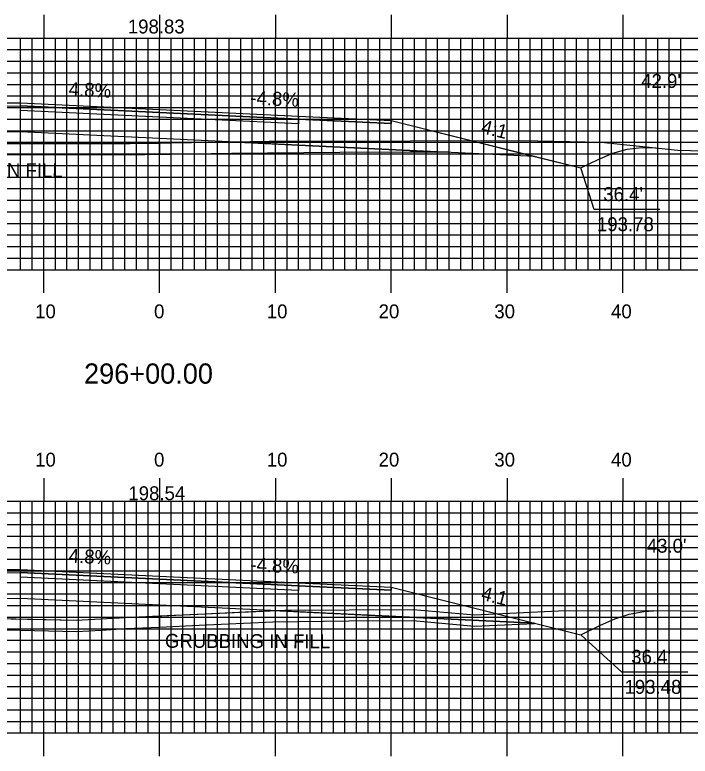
# Model space of a CAD drawing. Extents: x 1814522 to 1814865, y 442591 to 442811.
# Drawn here: x 1814675 to 1814733.3, y 442686.7 to 442750.7 of the extents above; entities that cross this region are included whole.
import ezdxf

# ---------------------------------------------------------------- set-up
doc = ezdxf.new("R2010")
doc.units = 0
for name, color, linetype in [('ANNOTATION', 7, 'Continuous'), ('D_Roadway_Centerline', 7, 'Continuous'), ('D_Roadway_Centerline_Text', 7, 'Continuous'), ('D_Roadway_Edge_Shoulder', 7, 'Continuous'), ('D_Roadway_Edge_TW', 7, 'Continuous'), ('D_Roadway_Pavement', 7, 'Continuous'), ('D_Roadway_SlopeLines', 7, 'Continuous'), ('D_Roadway_SubGrade', 7, 'Continuous'), ('D_Text_Standard', 7, 'Continuous'), ('GRUBBING IN FILL', 7, 'Continuous'), ('H_V ANNOTATION', 7, 'Continuous'), ('MAJOR', 7, 'Continuous'), ('MINOR', 7, 'Continuous'), ('S_Roadway_Centerline', 7, 'Continuous')]:
    doc.layers.add(name, color=color, linetype=linetype)

msp = doc.modelspace()

# ---------------------------------------------------------------- linework, layer by layer
at = {"layer": 'ANNOTATION'}
for points in [[(1814730.701, 442733.864), (1814725.009, 442733.864), (1814723.884, 442737.445)], [(1814733.115, 442693.92), (1814727.424, 442693.92), (1814723.884, 442697.147)]]:
    msp.add_lwpolyline(points, dxfattribs=at)
at = {"layer": 'D_Roadway_Centerline'}
for points in [[(1814653.448, 442739.4), (1814656.638, 442740.197), (1814667.508, 442742.915), (1814675.508, 442743.075), (1814687.508, 442742.499), (1814699.508, 442741.923), (1814707.508, 442741.539), (1814719.884, 442738.445), (1814723.884, 442737.445), (1814725.374, 442738.19), (1814726.624, 442738.721), (1814727.874, 442739.063), (1814729.124, 442739.217), (1814730.374, 442739.183)], [(1814652.747, 442698.927), (1814656.638, 442699.899), (1814667.508, 442702.617), (1814675.508, 442702.777), (1814687.508, 442702.201), (1814699.508, 442701.625), (1814707.508, 442701.241), (1814719.884, 442698.147), (1814723.884, 442697.147), (1814725.557, 442697.984), (1814726.807, 442698.531), (1814728.057, 442698.923), (1814729.307, 442699.16), (1814730.557, 442699.241)]]:
    msp.add_lwpolyline(points, dxfattribs=at)
at = {"layer": 'D_Roadway_Edge_Shoulder'}
for points in [[(1814675.508, 442743.075), (1814667.508, 442742.915), (1814667.508, 442742.665), (1814675.508, 442742.825)], [(1814699.508, 442741.923), (1814707.508, 442741.539), (1814707.508, 442741.289), (1814699.508, 442741.673)], [(1814675.508, 442702.777), (1814667.508, 442702.617), (1814667.508, 442702.367), (1814675.508, 442702.527)], [(1814699.508, 442701.625), (1814707.508, 442701.241), (1814707.508, 442700.991), (1814699.508, 442701.375)]]:
    msp.add_lwpolyline(points, close=True, dxfattribs=at)
at = {"layer": 'D_Roadway_Edge_TW'}
for points in [[(1814675.508, 442742.825), (1814675.508, 442743.075), (1814687.508, 442742.499), (1814699.508, 442741.923), (1814699.508, 442741.673), (1814687.508, 442742.249)], [(1814675.508, 442702.527), (1814675.508, 442702.777), (1814687.508, 442702.201), (1814699.508, 442701.625), (1814699.508, 442701.375), (1814687.508, 442701.951)]]:
    msp.add_lwpolyline(points, close=True, dxfattribs=at)
at = {"layer": 'D_Roadway_Pavement'}
for points in [[(1814675.508, 442742.408), (1814675.508, 442742.825), (1814687.508, 442742.249), (1814699.508, 442741.673), (1814699.508, 442741.256), (1814687.508, 442741.832)], [(1814675.508, 442702.11), (1814675.508, 442702.527), (1814687.508, 442701.951), (1814699.508, 442701.375), (1814699.508, 442700.958), (1814687.508, 442701.534)]]:
    msp.add_lwpolyline(points, close=True, dxfattribs=at)
at = {"layer": 'D_Roadway_SlopeLines'}
for points in [[(1814707.508, 442741.539), (1814723.884, 442737.445)], [(1814723.884, 442737.445), (1814725.374, 442738.19), (1814726.624, 442738.721), (1814727.874, 442739.063), (1814729.124, 442739.217), (1814730.374, 442739.183)], [(1814707.508, 442701.241), (1814723.884, 442697.147)], [(1814723.884, 442697.147), (1814725.557, 442697.984), (1814726.807, 442698.531), (1814728.057, 442698.923), (1814729.307, 442699.16), (1814730.557, 442699.241)]]:
    msp.add_lwpolyline(points, dxfattribs=at)
at = {"layer": 'D_Roadway_SubGrade'}
for points in [[(1814675.508, 442740.575), (1814656.638, 442740.197), (1814667.508, 442742.915), (1814667.508, 442742.665), (1814675.508, 442742.825), (1814687.508, 442742.249), (1814699.508, 442741.673), (1814707.508, 442741.289), (1814707.508, 442741.539), (1814719.884, 442738.445), (1814699.508, 442739.423), (1814687.508, 442739.999)], [(1814675.508, 442700.277), (1814656.638, 442699.899), (1814667.508, 442702.617), (1814667.508, 442702.367), (1814675.508, 442702.527), (1814687.508, 442701.951), (1814699.508, 442701.375), (1814707.508, 442700.991), (1814707.508, 442701.241), (1814719.884, 442698.147), (1814699.508, 442699.125), (1814687.508, 442699.701)]]:
    msp.add_lwpolyline(points, close=True, dxfattribs=at)
at = {"layer": 'GRUBBING IN FILL'}
for points in [[(1814656.638, 442739.528), (1814658.134, 442739.6), (1814671.642, 442739.571), (1814684.967, 442739.552), (1814687.508, 442739.596), (1814687.508, 442738.596), (1814684.975, 442738.552), (1814671.633, 442738.571), (1814658.291, 442738.591), (1814656.638, 442738.527)], [(1814656.638, 442739.528), (1814658.134, 442739.6), (1814671.642, 442739.571), (1814684.967, 442739.552), (1814687.508, 442739.596), (1814687.508, 442738.596), (1814684.975, 442738.552), (1814671.633, 442738.571), (1814658.291, 442738.591), (1814656.638, 442738.527)], [(1814687.508, 442739.596), (1814688.487, 442739.613), (1814693.703, 442739.701), (1814699.508, 442739.423), (1814709.696, 442738.934), (1814712.474, 442738.8), (1814709.167, 442738.797), (1814703.066, 442738.775), (1814693.703, 442738.701), (1814688.499, 442738.613), (1814687.508, 442738.596)], [(1814687.508, 442739.596), (1814688.487, 442739.613), (1814693.703, 442739.701), (1814699.508, 442739.423), (1814709.696, 442738.934), (1814712.474, 442738.8), (1814709.167, 442738.797), (1814703.066, 442738.775), (1814693.703, 442738.701), (1814688.499, 442738.613), (1814687.508, 442738.596)], [(1814687.508, 442698.782), (1814691.419, 442698.962), (1814697.283, 442699.232), (1814709.696, 442698.636), (1814719.884, 442698.147), (1814719.884, 442698.099), (1814714.679, 442697.853), (1814709.368, 442698.333), (1814703.85, 442698.306), (1814697.283, 442698.231), (1814690.933, 442697.938), (1814687.508, 442697.781)], [(1814687.508, 442698.782), (1814691.419, 442698.962), (1814697.283, 442699.232), (1814709.696, 442698.636), (1814719.884, 442698.147), (1814719.884, 442698.099), (1814714.679, 442697.853), (1814709.368, 442698.333), (1814703.85, 442698.306), (1814697.283, 442698.231), (1814690.933, 442697.938), (1814687.508, 442697.781)], [(1814656.638, 442698.871), (1814663.185, 442698.778), (1814671.839, 442698.589), (1814680.303, 442698.403), (1814684.531, 442698.645), (1814687.508, 442698.782), (1814687.508, 442697.781), (1814684.582, 442697.646), (1814682.451, 442697.525), (1814680.32, 442697.403), (1814671.838, 442697.589), (1814663.17, 442697.778), (1814656.638, 442697.871)], [(1814656.638, 442698.871), (1814663.185, 442698.778), (1814671.839, 442698.589), (1814680.303, 442698.403), (1814684.531, 442698.645), (1814687.508, 442698.782), (1814687.508, 442697.781), (1814684.582, 442697.646), (1814682.451, 442697.525), (1814680.32, 442697.403), (1814671.838, 442697.589), (1814663.17, 442697.778), (1814656.638, 442697.871)]]:
    msp.add_lwpolyline(points, close=True, dxfattribs=at)
at = {"layer": 'MAJOR'}
for p, q in [((1814677.508, 442750.669), (1814677.508, 442748.665)), ((1814687.508, 442750.669), (1814687.508, 442748.665)), ((1814697.508, 442750.669), (1814697.508, 442748.665)), ((1814707.508, 442750.669), (1814707.508, 442748.665)), ((1814717.508, 442750.669), (1814717.508, 442748.665)), ((1814727.508, 442750.669), (1814727.508, 442748.665)), ((1814547.508, 442748.665), (1814827.508, 442748.665)), ((1814547.508, 442748.665), (1814827.508, 442748.665)), ((1814677.508, 442728.665), (1814677.508, 442748.665)), ((1814687.508, 442728.665), (1814687.508, 442748.665)), ((1814697.508, 442728.665), (1814697.508, 442748.665)), ((1814707.508, 442728.665), (1814707.508, 442748.665)), ((1814717.508, 442728.665), (1814717.508, 442748.665)), ((1814727.508, 442728.665), (1814727.508, 442748.665)), ((1814547.508, 442743.665), (1814827.508, 442743.665)), ((1814547.508, 442738.665), (1814827.508, 442738.665)), ((1814547.508, 442733.665), (1814827.508, 442733.665)), ((1814547.508, 442728.665), (1814827.508, 442728.665)), ((1814547.508, 442728.665), (1814827.508, 442728.665)), ((1814677.508, 442726.661), (1814677.508, 442728.665)), ((1814687.508, 442726.661), (1814687.508, 442728.665)), ((1814697.508, 442726.661), (1814697.508, 442728.665)), ((1814707.508, 442726.661), (1814707.508, 442728.665)), ((1814717.508, 442726.661), (1814717.508, 442728.665)), ((1814727.508, 442726.661), (1814727.508, 442728.665)), ((1814677.508, 442710.669), (1814677.508, 442708.665)), ((1814687.508, 442710.669), (1814687.508, 442708.665)), ((1814697.508, 442710.669), (1814697.508, 442708.665)), ((1814707.508, 442710.669), (1814707.508, 442708.665)), ((1814717.508, 442710.669), (1814717.508, 442708.665)), ((1814727.508, 442710.669), (1814727.508, 442708.665)), ((1814547.508, 442708.665), (1814827.508, 442708.665)), ((1814547.508, 442708.665), (1814827.508, 442708.665)), ((1814677.508, 442688.665), (1814677.508, 442708.665)), ((1814687.508, 442688.665), (1814687.508, 442708.665)), ((1814697.508, 442688.665), (1814697.508, 442708.665)), ((1814707.508, 442688.665), (1814707.508, 442708.665)), ((1814717.508, 442688.665), (1814717.508, 442708.665)), ((1814727.508, 442688.665), (1814727.508, 442708.665)), ((1814547.508, 442703.665), (1814827.508, 442703.665)), ((1814547.508, 442698.665), (1814827.508, 442698.665)), ((1814547.508, 442693.665), (1814827.508, 442693.665)), ((1814547.508, 442688.665), (1814827.508, 442688.665)), ((1814547.508, 442688.665), (1814827.508, 442688.665)), ((1814677.508, 442686.661), (1814677.508, 442688.665)), ((1814687.508, 442686.661), (1814687.508, 442688.665)), ((1814697.508, 442686.661), (1814697.508, 442688.665)), ((1814707.508, 442686.661), (1814707.508, 442688.665)), ((1814717.508, 442686.661), (1814717.508, 442688.665)), ((1814727.508, 442686.661), (1814727.508, 442688.665))]:
    msp.add_line(p, q, dxfattribs=at)
at = {"layer": 'MINOR'}
for p, q in [((1814675.508, 442728.665), (1814675.508, 442748.665)), ((1814676.508, 442728.665), (1814676.508, 442748.665)), ((1814678.508, 442728.665), (1814678.508, 442748.665)), ((1814679.508, 442728.665), (1814679.508, 442748.665)), ((1814680.508, 442728.665), (1814680.508, 442748.665)), ((1814681.508, 442728.665), (1814681.508, 442748.665)), ((1814682.508, 442728.665), (1814682.508, 442748.665)), ((1814683.508, 442728.665), (1814683.508, 442748.665)), ((1814684.508, 442728.665), (1814684.508, 442748.665)), ((1814685.508, 442728.665), (1814685.508, 442748.665)), ((1814686.508, 442728.665), (1814686.508, 442748.665)), ((1814688.508, 442728.665), (1814688.508, 442748.665)), ((1814689.508, 442728.665), (1814689.508, 442748.665)), ((1814690.508, 442728.665), (1814690.508, 442748.665)), ((1814691.508, 442728.665), (1814691.508, 442748.665)), ((1814692.508, 442728.665), (1814692.508, 442748.665)), ((1814693.508, 442728.665), (1814693.508, 442748.665)), ((1814694.508, 442728.665), (1814694.508, 442748.665)), ((1814695.508, 442728.665), (1814695.508, 442748.665)), ((1814696.508, 442728.665), (1814696.508, 442748.665)), ((1814698.508, 442728.665), (1814698.508, 442748.665)), ((1814699.508, 442728.665), (1814699.508, 442748.665)), ((1814700.508, 442728.665), (1814700.508, 442748.665)), ((1814701.508, 442728.665), (1814701.508, 442748.665)), ((1814702.508, 442728.665), (1814702.508, 442748.665)), ((1814703.508, 442728.665), (1814703.508, 442748.665)), ((1814704.508, 442728.665), (1814704.508, 442748.665)), ((1814705.508, 442728.665), (1814705.508, 442748.665)), ((1814706.508, 442728.665), (1814706.508, 442748.665)), ((1814708.508, 442728.665), (1814708.508, 442748.665)), ((1814709.508, 442728.665), (1814709.508, 442748.665)), ((1814710.508, 442728.665), (1814710.508, 442748.665)), ((1814711.508, 442728.665), (1814711.508, 442748.665)), ((1814712.508, 442728.665), (1814712.508, 442748.665)), ((1814713.508, 442728.665), (1814713.508, 442748.665)), ((1814714.508, 442728.665), (1814714.508, 442748.665)), ((1814715.508, 442728.665), (1814715.508, 442748.665)), ((1814716.508, 442728.665), (1814716.508, 442748.665)), ((1814718.508, 442728.665), (1814718.508, 442748.665)), ((1814719.508, 442728.665), (1814719.508, 442748.665)), ((1814720.508, 442728.665), (1814720.508, 442748.665)), ((1814721.508, 442728.665), (1814721.508, 442748.665)), ((1814722.508, 442728.665), (1814722.508, 442748.665)), ((1814723.508, 442728.665), (1814723.508, 442748.665)), ((1814724.508, 442728.665), (1814724.508, 442748.665)), ((1814725.508, 442728.665), (1814725.508, 442748.665)), ((1814726.508, 442728.665), (1814726.508, 442748.665)), ((1814728.508, 442728.665), (1814728.508, 442748.665)), ((1814729.508, 442728.665), (1814729.508, 442748.665)), ((1814730.508, 442728.665), (1814730.508, 442748.665)), ((1814731.508, 442728.665), (1814731.508, 442748.665)), ((1814732.508, 442728.665), (1814732.508, 442748.665)), ((1814547.508, 442747.665), (1814827.508, 442747.665)), ((1814547.508, 442746.665), (1814827.508, 442746.665)), ((1814547.508, 442745.665), (1814827.508, 442745.665)), ((1814547.508, 442744.665), (1814827.508, 442744.665)), ((1814547.508, 442742.665), (1814827.508, 442742.665)), ((1814547.508, 442741.665), (1814827.508, 442741.665)), ((1814547.508, 442740.665), (1814827.508, 442740.665)), ((1814547.508, 442739.665), (1814827.508, 442739.665)), ((1814547.508, 442737.665), (1814827.508, 442737.665)), ((1814547.508, 442736.665), (1814827.508, 442736.665)), ((1814547.508, 442735.665), (1814827.508, 442735.665)), ((1814547.508, 442734.665), (1814827.508, 442734.665)), ((1814547.508, 442732.665), (1814827.508, 442732.665)), ((1814547.508, 442731.665), (1814827.508, 442731.665)), ((1814547.508, 442730.665), (1814827.508, 442730.665)), ((1814547.508, 442729.665), (1814827.508, 442729.665)), ((1814675.508, 442688.665), (1814675.508, 442708.665)), ((1814676.508, 442688.665), (1814676.508, 442708.665)), ((1814678.508, 442688.665), (1814678.508, 442708.665)), ((1814679.508, 442688.665), (1814679.508, 442708.665)), ((1814680.508, 442688.665), (1814680.508, 442708.665)), ((1814681.508, 442688.665), (1814681.508, 442708.665)), ((1814682.508, 442688.665), (1814682.508, 442708.665)), ((1814683.508, 442688.665), (1814683.508, 442708.665)), ((1814684.508, 442688.665), (1814684.508, 442708.665)), ((1814685.508, 442688.665), (1814685.508, 442708.665)), ((1814686.508, 442688.665), (1814686.508, 442708.665)), ((1814688.508, 442688.665), (1814688.508, 442708.665)), ((1814689.508, 442688.665), (1814689.508, 442708.665)), ((1814690.508, 442688.665), (1814690.508, 442708.665)), ((1814691.508, 442688.665), (1814691.508, 442708.665)), ((1814692.508, 442688.665), (1814692.508, 442708.665)), ((1814693.508, 442688.665), (1814693.508, 442708.665)), ((1814694.508, 442688.665), (1814694.508, 442708.665)), ((1814695.508, 442688.665), (1814695.508, 442708.665)), ((1814696.508, 442688.665), (1814696.508, 442708.665)), ((1814698.508, 442688.665), (1814698.508, 442708.665)), ((1814699.508, 442688.665), (1814699.508, 442708.665)), ((1814700.508, 442688.665), (1814700.508, 442708.665)), ((1814701.508, 442688.665), (1814701.508, 442708.665)), ((1814702.508, 442688.665), (1814702.508, 442708.665)), ((1814703.508, 442688.665), (1814703.508, 442708.665)), ((1814704.508, 442688.665), (1814704.508, 442708.665)), ((1814705.508, 442688.665), (1814705.508, 442708.665)), ((1814706.508, 442688.665), (1814706.508, 442708.665)), ((1814708.508, 442688.665), (1814708.508, 442708.665)), ((1814709.508, 442688.665), (1814709.508, 442708.665)), ((1814710.508, 442688.665), (1814710.508, 442708.665)), ((1814711.508, 442688.665), (1814711.508, 442708.665)), ((1814712.508, 442688.665), (1814712.508, 442708.665)), ((1814713.508, 442688.665), (1814713.508, 442708.665)), ((1814714.508, 442688.665), (1814714.508, 442708.665)), ((1814715.508, 442688.665), (1814715.508, 442708.665)), ((1814716.508, 442688.665), (1814716.508, 442708.665)), ((1814718.508, 442688.665), (1814718.508, 442708.665)), ((1814719.508, 442688.665), (1814719.508, 442708.665)), ((1814720.508, 442688.665), (1814720.508, 442708.665)), ((1814721.508, 442688.665), (1814721.508, 442708.665)), ((1814722.508, 442688.665), (1814722.508, 442708.665)), ((1814723.508, 442688.665), (1814723.508, 442708.665)), ((1814724.508, 442688.665), (1814724.508, 442708.665)), ((1814725.508, 442688.665), (1814725.508, 442708.665)), ((1814726.508, 442688.665), (1814726.508, 442708.665)), ((1814728.508, 442688.665), (1814728.508, 442708.665)), ((1814729.508, 442688.665), (1814729.508, 442708.665)), ((1814730.508, 442688.665), (1814730.508, 442708.665)), ((1814731.508, 442688.665), (1814731.508, 442708.665)), ((1814732.508, 442688.665), (1814732.508, 442708.665)), ((1814547.508, 442707.665), (1814827.508, 442707.665)), ((1814547.508, 442706.665), (1814827.508, 442706.665)), ((1814547.508, 442705.665), (1814827.508, 442705.665)), ((1814547.508, 442704.665), (1814827.508, 442704.665)), ((1814547.508, 442702.665), (1814827.508, 442702.665)), ((1814547.508, 442701.665), (1814827.508, 442701.665)), ((1814547.508, 442700.665), (1814827.508, 442700.665)), ((1814547.508, 442699.665), (1814827.508, 442699.665)), ((1814547.508, 442697.665), (1814827.508, 442697.665)), ((1814547.508, 442696.665), (1814827.508, 442696.665)), ((1814547.508, 442695.665), (1814827.508, 442695.665)), ((1814547.508, 442694.665), (1814827.508, 442694.665)), ((1814547.508, 442692.665), (1814827.508, 442692.665)), ((1814547.508, 442691.665), (1814827.508, 442691.665)), ((1814547.508, 442690.665), (1814827.508, 442690.665)), ((1814547.508, 442689.665), (1814827.508, 442689.665))]:
    msp.add_line(p, q, dxfattribs=at)
at = {"layer": 'S_Roadway_Centerline'}
for points in [[(1814547.508, 442736.831), (1814557.042, 442737.108), (1814559.077, 442737.2), (1814562.028, 442737.26), (1814576.198, 442737.904), (1814586.683, 442738.796), (1814593.172, 442738.958), (1814599.985, 442738.663), (1814608.419, 442738.425), (1814620.662, 442739.175), (1814625.399, 442739.21), (1814629.103, 442739.434), (1814642.752, 442738.971), (1814656.576, 442739.525), (1814658.134, 442739.6), (1814658.317, 442739.591), (1814684.967, 442739.552), (1814692.006, 442739.674), (1814696.955, 442739.753), (1814709.165, 442739.797), (1814718.813, 442739.807), (1814725.616, 442739.672), (1814732.236, 442738.992), (1814742.086, 442738.733)], [(1814547.508, 442697.837), (1814549.775, 442697.725), (1814555.438, 442697.738), (1814566.513, 442698.088), (1814573.411, 442698.426), (1814590, 442699.042), (1814598.779, 442699.54), (1814610.82, 442698.849), (1814614.579, 442698.703), (1814628.995, 442698.398), (1814631.137, 442698.395), (1814644.071, 442698.878), (1814647.187, 442699.006), (1814663.185, 442698.778), (1814663.374, 442698.775), (1814680.303, 442698.403), (1814684.531, 442698.645), (1814698.307, 442699.279), (1814709.411, 442699.333), (1814714.7, 442698.855), (1814721.941, 442699.198), (1814730.176, 442699.246), (1814739.585, 442699.133)]]:
    msp.add_lwpolyline(points, dxfattribs=at)

# ---------------------------------------------------------------- texts
at = {"layer": 'ANNOTATION'}
for s, rotation, p in [('4.8%', 357.25191, (1814679.637, 442743.679)), ('-4.8%', 357.25191, (1814695.316, 442742.926)), ('4:1', 345.96376, (1814715.202, 442740.477)), ('4.8%', 357.25191, (1814679.637, 442703.381)), ('-4.8%', 357.25191, (1814695.316, 442702.628)), ('4:1', 345.96376, (1814715.202, 442700.179))]:
    msp.add_text(s, height=1.2, rotation=rotation, dxfattribs=at).set_placement(p)
for s, p in [("36.4'", (1814725.808, 442734.59)), ('193.78', (1814725.262, 442731.99)), ("36.4'", (1814728.223, 442694.646)), ('193.48', (1814727.645, 442692.046))]:
    msp.add_text(s, height=1.2, dxfattribs=at).set_placement(p)
at = {"layer": 'D_Roadway_Centerline'}
for s, p in [('C', (1814687.502, 442742.499)), ('L', (1814687.508, 442742.491)), ('C', (1814687.502, 442702.201)), ('L', (1814687.508, 442702.194))]:
    msp.add_text(s, height=0.0146, dxfattribs=at).set_placement(p)
at = {"layer": 'D_Roadway_Centerline_Text'}
for s, p in [('198.83', (1814684.763, 442749.06)), ('198.54', (1814684.811, 442708.762))]:
    msp.add_text(s, height=1.2, dxfattribs=at).set_placement(p)
at = {"layer": 'D_Text_Standard'}
for s, p in [("42.9'", (1814729.084, 442744.362)), ("43.0'", (1814729.566, 442704.23))]:
    msp.add_text(s, height=1.2, dxfattribs=at).set_placement(p)
at = {"layer": 'GRUBBING IN FILL'}
for p in [(1814664.868, 442736.695), (1814687.964, 442696.023)]:
    msp.add_text('GRUBBING IN FILL', height=1.2, rotation=359.80532, dxfattribs=at).set_placement(p)
at = {"layer": 'H_V ANNOTATION'}
for s, height, p in [('10', 1.2, (1814676.758, 442724.465)), ('0', 1.2, (1814687.026, 442724.465)), ('10', 1.2, (1814696.758, 442724.465)), ('20', 1.2, (1814706.415, 442724.465)), ('30', 1.2, (1814716.405, 442724.465)), ('40', 1.2, (1814726.48, 442724.465)), ('296+00.00', 1.75, (1814680.984, 442718.821)), ('10', 1.2, (1814676.758, 442711.665)), ('0', 1.2, (1814687.026, 442711.665)), ('10', 1.2, (1814696.758, 442711.665)), ('20', 1.2, (1814706.415, 442711.665)), ('30', 1.2, (1814716.405, 442711.665)), ('40', 1.2, (1814726.48, 442711.665))]:
    msp.add_text(s, height=height, dxfattribs=at).set_placement(p)

doc.saveas('drawing.dxf')
